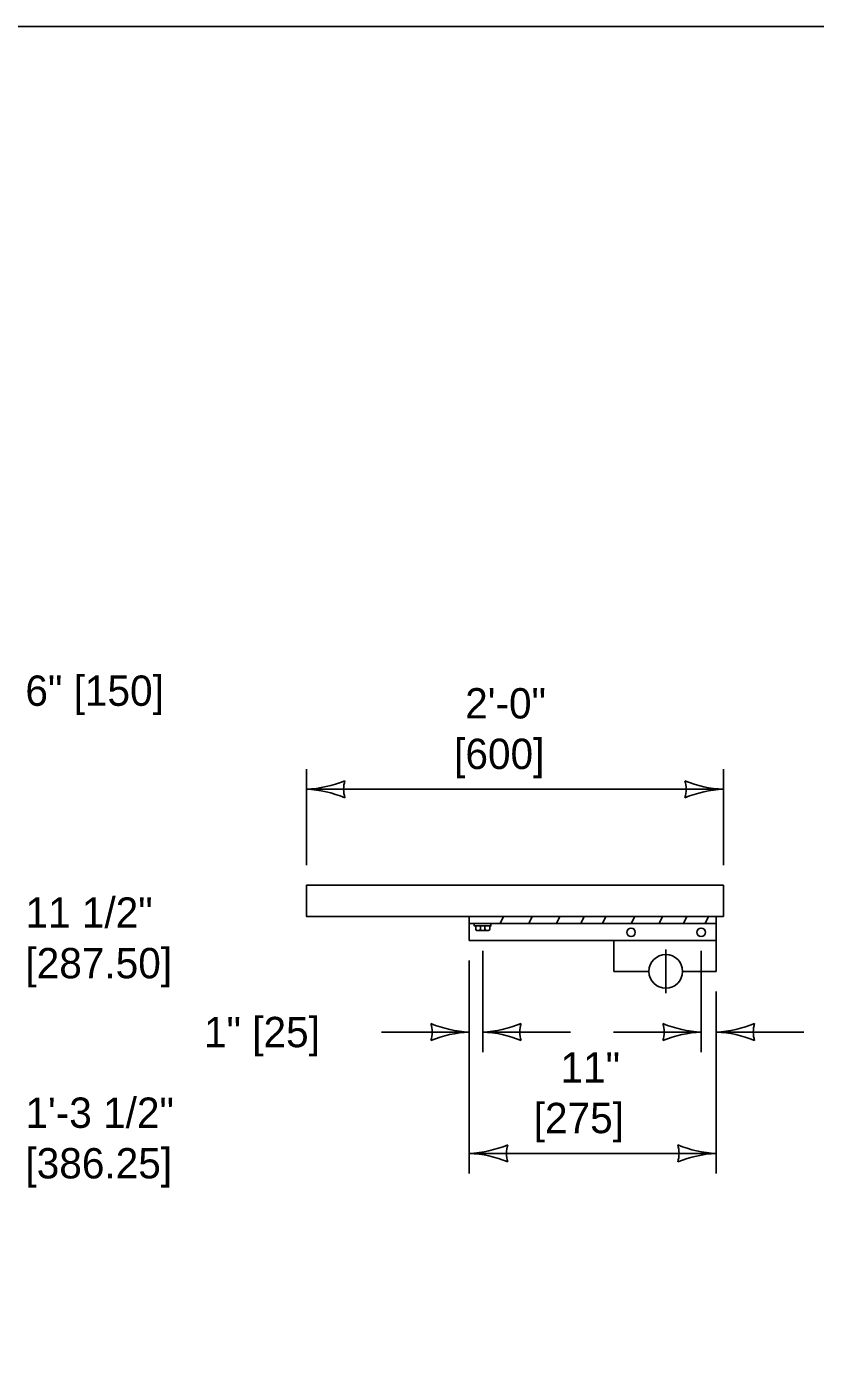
# Model space of a CAD drawing. Extents: x 49991.4 to 50021, y 49987.6 to 50011.4.
# Drawn here: x 50011.058 to 50012.618, y 49996.384 to 49998.999 of the extents above; entities that cross this region are included whole.
import ezdxf

# ---------------------------------------------------------------- set-up
doc = ezdxf.new("R2010")
doc.units = 0
for name, color, linetype in [('Level 1', 7, 'Continuous'), ('Level 2', 7, 'Continuous'), ('Level 3', 7, 'Continuous'), ('Level 5', 7, 'Continuous')]:
    doc.layers.add(name, color=color, linetype=linetype)

msp = doc.modelspace()

# ---------------------------------------------------------------- linework, layer by layer
at = {"layer": 'Level 1'}
for p, q in [((50011.9336, 49997.1916), (50011.9336, 49997.2389)), ((50011.9944, 49997.2248), (50012.001, 49997.2389)), ((50012.0512, 49997.2248), (50012.0578, 49997.2389)), ((50012.1062, 49997.2248), (50012.1128, 49997.2389)), ((50012.1542, 49997.2248), (50012.1608, 49997.2389)), ((50012.1972, 49997.2248), (50012.2039, 49997.2389)), ((50012.254, 49997.2248), (50012.2607, 49997.2389)), ((50012.309, 49997.2248), (50012.3157, 49997.2389)), ((50012.357, 49997.2248), (50012.3637, 49997.2389)), ((50012.4001, 49997.2248), (50012.4067, 49997.2389)), ((50012.4218, 49997.2389), (50012.4218, 49997.1303)), ((50011.9336, 49997.2248), (50012.4218, 49997.2248)), ((50011.9463, 49997.2138), (50011.9463, 49997.2201)), ((50011.9489, 49997.2112), (50011.9715, 49997.2112)), ((50011.9555, 49997.2137), (50011.9555, 49997.2201)), ((50011.9647, 49997.2137), (50011.9647, 49997.2201)), ((50011.974, 49997.2138), (50011.974, 49997.2201)), ((50011.9336, 49997.1916), (50012.2192, 49997.1916)), ((50012.2192, 49997.1916), (50012.4218, 49997.1916)), ((50012.2192, 49997.1303), (50012.2192, 49997.1916)), ((50012.2192, 49997.1303), (50012.289, 49997.1303)), ((50012.3554, 49997.1303), (50012.4218, 49997.1303))]:
    msp.add_line(p, q, dxfattribs=at)
for points in [[(49999.3835, 49998.9992), (50016.7501, 49998.9992), (50016.7501, 49987.7988), (49999.3835, 49987.7988)], [(50012.436, 49997.3005), (50012.436, 49997.2389), (50011.6118, 49997.2389), (50011.6118, 49997.3005)], [(50011.9436, 49997.2248), (50011.9436, 49997.2201), (50011.9764, 49997.2201), (50011.9764, 49997.2248)]]:
    msp.add_lwpolyline(points, close=True, dxfattribs=at)
for centre, radius in [((50012.2535, 49997.2075), 0.00843), ((50012.3921, 49997.2075), 0.00843), ((50012.3222, 49997.1303), 0.0333)]:
    msp.add_circle(centre, radius, dxfattribs=at)
for centre, start, end in [((50011.9489, 49997.2137), 180, 270), ((50011.953, 49997.2137), 270, 0), ((50011.9581, 49997.2137), 180, 270), ((50011.9622, 49997.2137), 270, 0), ((50011.9673, 49997.2137), 180, 270), ((50011.9714, 49997.2137), 270, 0)]:
    msp.add_arc(centre, 0.00257, start, end, dxfattribs=at)
at = {"layer": 'Level 3'}
for p, q in [((50011.6118, 49997.3405), (50011.6118, 49997.5305)), ((50012.436, 49997.3405), (50012.436, 49997.5305)), ((50011.6118, 49997.4905), (50012.436, 49997.4905)), ((50011.9336, 49996.7303), (50011.9336, 49997.1516)), ((50011.9602, 49996.9703), (50011.9602, 49997.1712)), ((50012.3923, 49996.9703), (50012.3923, 49997.1712)), ((50012.4218, 49996.7303), (50012.4218, 49997.0903)), ((50011.7602, 49997.0103), (50011.9336, 49997.0103)), ((50011.9602, 49997.0103), (50012.1336, 49997.0103)), ((50012.2189, 49997.0103), (50012.3923, 49997.0103)), ((50012.4218, 49997.0103), (50012.5952, 49997.0103)), ((50011.9341, 49996.7703), (50012.4218, 49996.7703))]:
    msp.add_line(p, q, dxfattribs=at)
for centre, radius, start, end in [((50011.6003, 49997.7232), 0.233, 272.8273, 292.0772), ((50011.6026, 49997.2684), 0.2223, 67.456, 87.6395), ((50011.74, 49997.4905), 0.0548, 162.1388, 197.8612), ((50012.4452, 49997.7126), 0.2223, 247.456, 267.6395), ((50012.3078, 49997.4905), 0.0548, 342.1388, 17.8612), ((50012.4475, 49997.2578), 0.233, 92.8273, 112.0772), ((50011.9428, 49997.2324), 0.2223, 247.456, 267.6395), ((50011.8054, 49997.0103), 0.0548, 342.1388, 17.8612), ((50011.9487, 49997.243), 0.233, 272.8273, 292.0772), ((50012.0884, 49997.0103), 0.0548, 162.1388, 197.8612), ((50012.4015, 49997.2324), 0.2223, 247.456, 267.6395), ((50012.2641, 49997.0103), 0.0548, 342.1388, 17.8612), ((50012.4103, 49997.243), 0.233, 272.8273, 292.0772), ((50012.55, 49997.0103), 0.0548, 162.1388, 197.8612), ((50011.9451, 49996.7776), 0.233, 92.8273, 112.0772), ((50011.951, 49996.7882), 0.2223, 67.456, 87.6395), ((50012.4038, 49996.7776), 0.233, 92.8273, 112.0772), ((50012.4126, 49996.7882), 0.2223, 67.456, 87.6395), ((50011.9221, 49997.003), 0.233, 272.8273, 292.0772), ((50012.0618, 49996.7703), 0.0548, 162.1388, 197.8612), ((50012.431, 49996.9924), 0.2223, 247.456, 267.6395), ((50012.2936, 49996.7703), 0.0548, 342.1388, 17.8612), ((50011.9244, 49996.5482), 0.2223, 67.456, 87.6395), ((50012.4333, 49996.5376), 0.233, 92.8273, 112.0772)]:
    msp.add_arc(centre, radius, start, end, dxfattribs=at)
at = {"layer": 'Level 5'}
msp.add_line((50012.3221, 49997.1736), (50012.3221, 49997.0871), dxfattribs=at)

# ---------------------------------------------------------------- texts
at = {"layer": 'Level 2'}
for s, p in [('6" [150]', (50011.056, 49997.6555)), ('2\'-0"', (50011.9255, 49997.6305)), ('[600]', (50011.9037, 49997.5305)), ('11 1/2"', (50011.0561, 49997.2166)), ('[287.50]', (50011.0561, 49997.1166)), ('1" [25]', (50011.4091, 49996.9803)), ('11"', (50012.114, 49996.9103)), ('1\'-3 1/2"', (50011.0561, 49996.8208)), ('[275]', (50012.061, 49996.8103)), ('[386.25]', (50011.0561, 49996.7208))]:
    msp.add_text(s, height=0.06, dxfattribs=at).set_placement(p)

doc.saveas('drawing.dxf')
